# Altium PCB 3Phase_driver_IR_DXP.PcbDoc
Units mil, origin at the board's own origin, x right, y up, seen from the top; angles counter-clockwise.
Board outline 4578 x 5356 mil, 2 copper layers (Top Layer, Bottom Layer); 86 components, 55 nets, 275 pads, 76 vias.
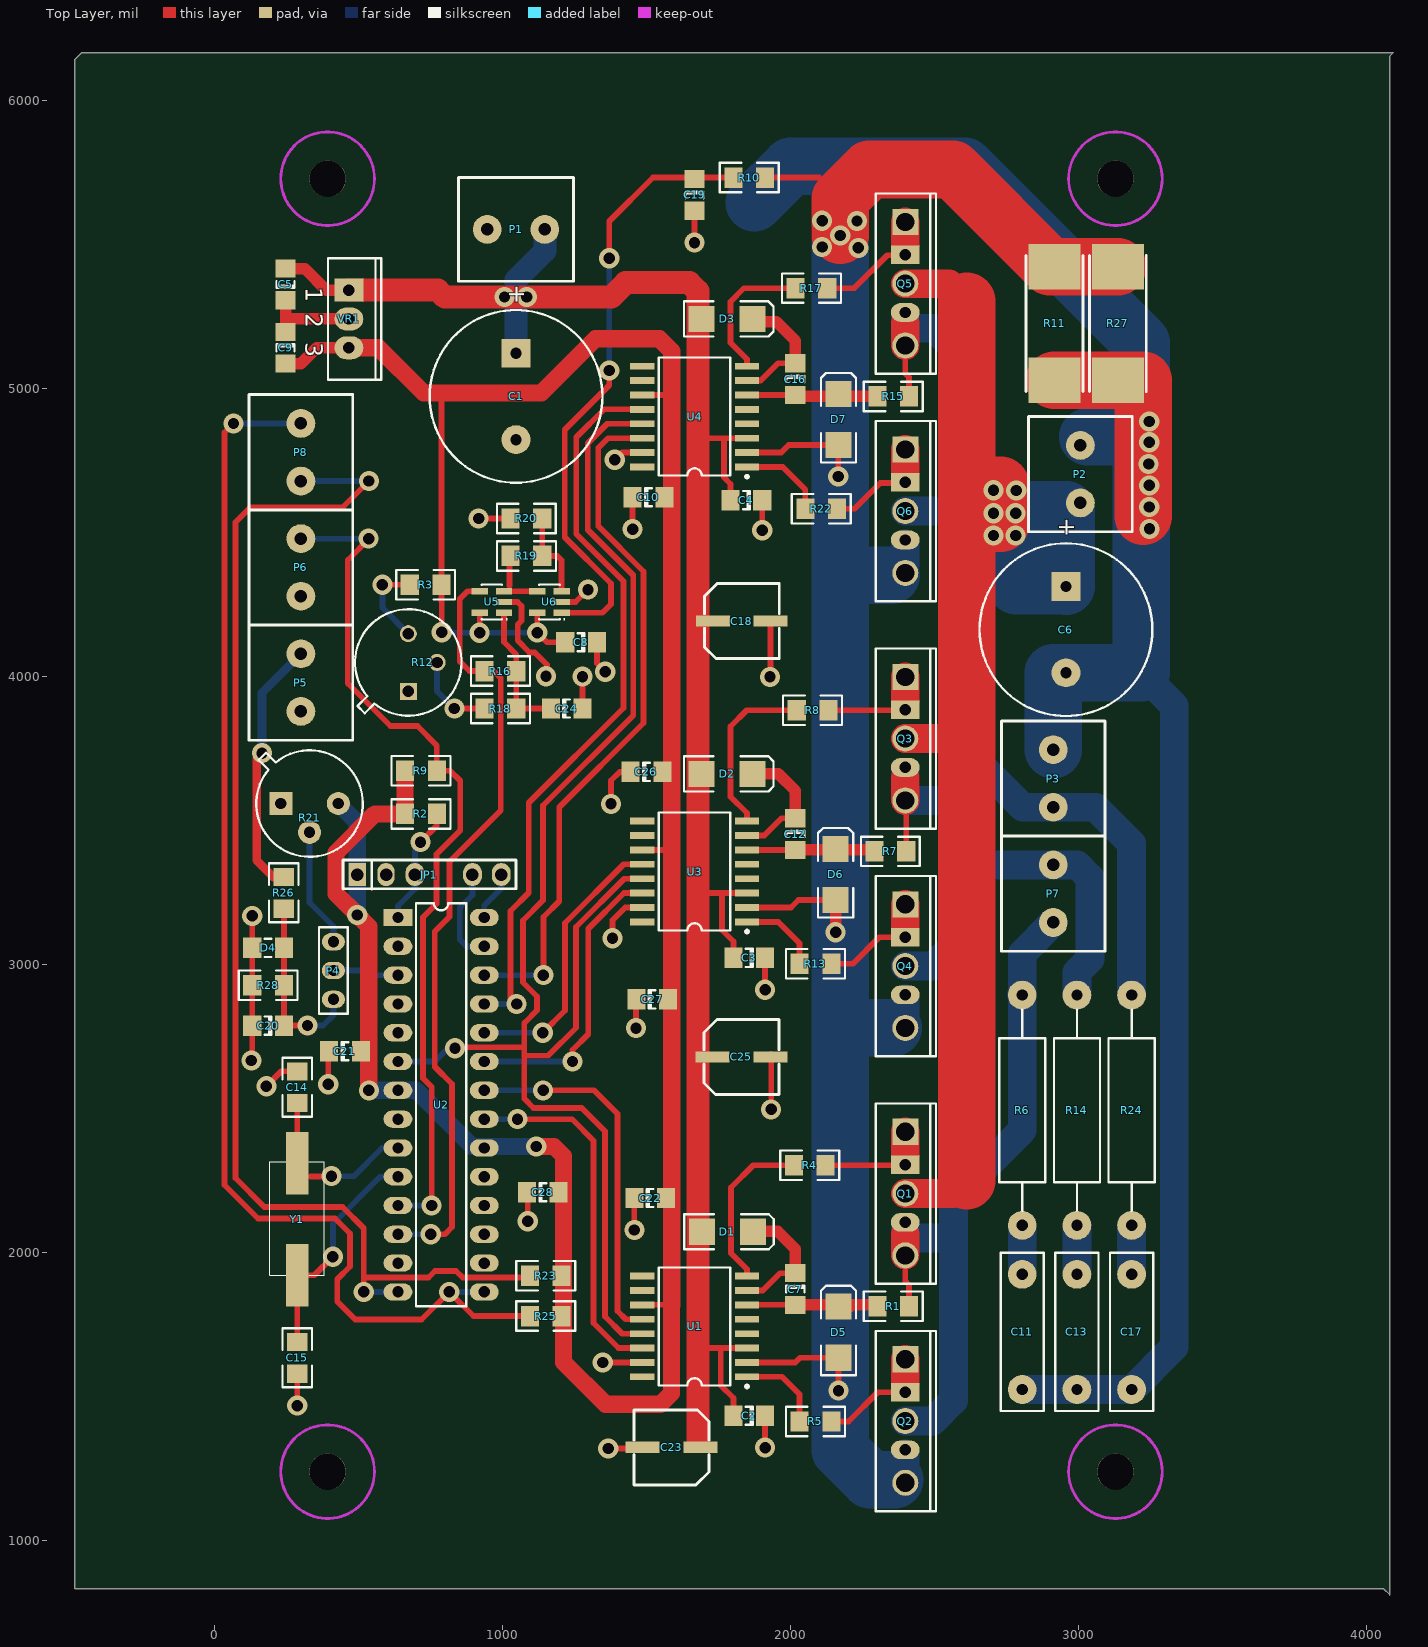
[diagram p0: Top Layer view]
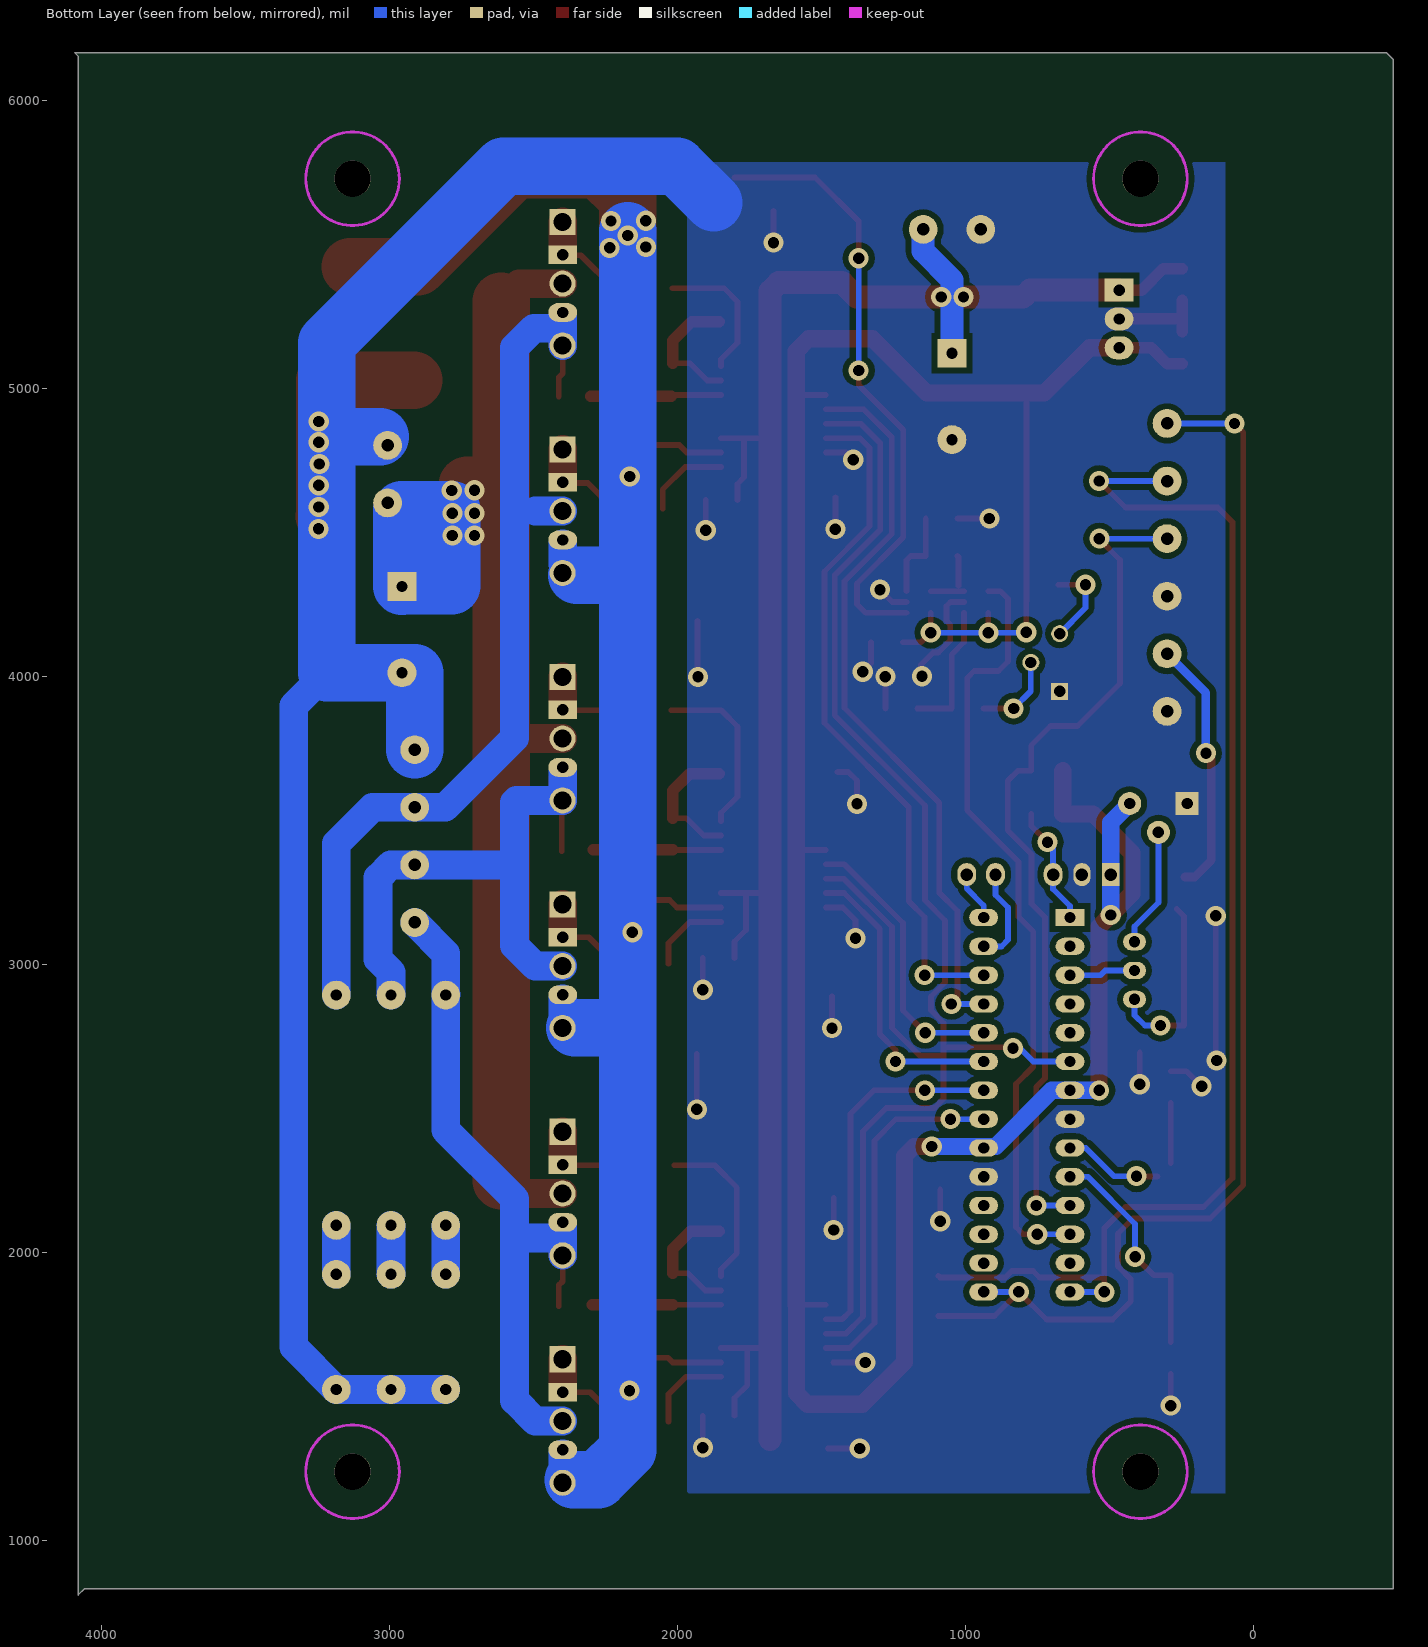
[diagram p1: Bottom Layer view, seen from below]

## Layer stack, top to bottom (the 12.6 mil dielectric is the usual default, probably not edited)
Top Layer: signal copper 1.4
Dielectric: dielectric 12.6, FR-4, Dk 4.8
Bottom Layer: signal copper 1.4

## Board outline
-484,833 4061,833 4083,811 4083,6156 4094,6167 -462,6167 -484,6145 -484,833

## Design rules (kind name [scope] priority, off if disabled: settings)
Clearance [All] p1: gap=10
PlaneConnect [All] p1: planeconnectstyle=Direct reliefexpansion=20 reliefentries=4 reliefconductorwidth=10 reliefairgap=10
PolygonConnect [All] p1: connectstyle=Direct reliefconductorwidth=10 reliefentries=4 polygonreliefangle="90 Angle"
RoutingVias [All] p1: holewidth=40 width=70 viastyle="Through Hole" minholewidth=28 minwidth=50 maxholewidth=50 maxwidth=100
SilkscreenOverComponentPads [All] p1: minsilkscreentomaskgap=10
SolderMaskExpansion [All] p1: expansion=4
TestPointUsage [All] p1: valid=0 allowmultiple=FALSE
Testpoint [All] p1: side=15 testpointundercomponent=TRUE minsize=40 maxsize=100 preferedsize=60 minholesize=0 maxholesize=40 preferedholesize=32 testpointgrid=1 style=1023 order=0123456789
Width [All] p1: maxlimit=200 minlimit=10 preferedwidth=10 toplayer_prefwidth=20 bottomlayer_prefwidth=20 minimp=50.000000 maximp=50.000000 favimp=50.000000
22 further rules are at their usual default settings.

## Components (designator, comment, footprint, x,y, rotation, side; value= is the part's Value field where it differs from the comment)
C1 "1000uF" RB7.6-15 1048,4974 r90 top
C2 "Cap Semi" C1206 1858,1434 r180 top
C3 "Cap Semi" C1206 1858,3024 r180 top
C4 "Cap Semi" C1206 1848,4614 r180 top
C5 "Cap Semi" C1206 247.57,5363 r90 top
C6 "1000uF" RB7.6-15 2958,4164 r90 top
C7 "Cap Semi" C1206 2018,1874 r270 top
C8 "Cap Semi" C1206 1274,4120 r180 top
C9 "Cap Semi" C1206 247.57,5143 r270 top
C10 "Cap Semi" C1206 1508,4624 r0 top
C11 "Cap Semi" RAD-0.4 2806,1725 r270 top
C12 "Cap Semi" C1206 2018,3454 r270 top
C13 "Cap Semi" RAD-0.4 2996,1725 r270 top
C14 "15pF" C3216-1206 288,2575 r270 top
C15 "15pF" C3216-1206 288,1635 r90 top
C16 "Cap Semi" C1206 2018,5034 r270 top
C17 "Cap Semi" RAD-0.4 3186,1725 r270 top
C18 "Cap Semi" NACZ63x8 1702,4194 r0 top
C19 "Cap Semi" C1206 1668,5674 r270 top
C20 "Cap Semi" C1206 187,2789 r180 top
C21 "Cap Semi" C1206 454,2700 r0 top
C22 "Cap Semi" C1206 1514,2190 r0 top
C23 "Cap Semi" NACZ63x8 1718,1324 r180 top
C24 "Cap Semi" C1206 1224,3890 r0 top
C25 "Cap Semi" NACZ63x8 1701,2680 r0 top
C26 "Cap Semi" C1206 1501,3670 r0 top
C27 "Cap Semi" C1206 1521,2880 r0 top
C28 "Cap Semi" C1206 1141,2210 r0 top
D1 "Diode" SMB 1782,2073 r0 top
D2 "Diode" SMB 1781,3663 r0 top
D3 "Diode" SMB 1781,5243 r0 top
D4 "D Zener" CR3216-1206 187,3059 r0 top
D5 "Diode" SMB 2168,1724 r90 top
D6 "Diode" SMB 2158,3314 r90 top
D7 "Diode" SMB 2168,4894 r90 top
JP1 "Tuskesor 6x1" SIP6P 498,3314 r0 top
P1 "Header 2" AKZ350/2-5.08 1148,5554 r180 top
P2 "Header 2" AKZ350/2-5.08 3008,4604 r90 top
P3 "Header 2" AKZ250_2 2914,3747 r270 top
P4 "Header 3" HDR1X3 414,3080 r270 top
P5 "Header 2" AKZ250_2 301,4080 r270 top
P6 "Header 2" AKZ250_2 301,4480 r270 top
P7 "Header 2" AKZ250_2 2914,3347 r270 top
P8 "Header 2" AKZ250_2 301,4680 r90 top
Q1 "MOSFET-N" TO-247_220 2400,2205.57 r270 top
Q2 "MOSFET-N" TO-247_220 2400,1415.57 r270 top
Q3 "MOSFET-N" TO-247_220 2400,3785.57 r270 top
Q4 "MOSFET-N" TO-247_220 2400,2995.57 r270 top
Q5 "MOSFET-N" TO-247_220 2400,5365.57 r270 top
Q6 "MOSFET-N" TO-247_220 2400,4575.57 r270 top
R1 "Res1" C3216-1206 2358,1814 r0 top
R2 "Res1" C3216-1206 718,3524 r180 top
R3 "Res1" C3216-1206 734,4320 r0 top
R4 "Res1" C3216-1206 2068,2304 r180 top
R5 "Res1" C3216-1206 2088,1414 r180 top
R6 "Res1" AXIAL-0.8 2806,2495 r270 top
R7 "Res1" C3216-1206 2348,3394 r0 top
R8 "Res1" C3216-1206 2078,3884 r180 top
R9 "Res1" C3216-1206 718,3674 r180 top
R10 "Res1" C3216-1206 1858,5734 r0 top
R11 "Res1" RWC5020 2918,5464 r270 top
R12 "RPot1" TO-205AF#1 674,4050 r90 top
R13 "Res1" C3216-1206 2088,3004 r180 top
R14 "Res1" AXIAL-0.8 2996,2495 r270 top
R15 "Res1" C3216-1206 2358,4974 r0 top
R16 "Res1" C3216-1206 994,4020 r180 top
R17 "Res1" C3216-1206 2074,5350 r180 top
R18 "Res1" C3216-1206 994,3890 r180 top
R19 "Res1" C3216-1206 1084,4420 r0 top
R20 "Res1" C3216-1206 1084,4550 r180 top
R21 "RPot1" TO-205AF#2 331,3560 r0 top
R22 "Res1" C3216-1206 2108,4584 r180 top
R23 "Res1" C3216-1206 1151,1920 r0 top
R24 "Res1" AXIAL-0.8 3186,2495 r270 top
R25 "Res1" C3216-1206 1151,1780 r0 top
R26 "Res1" C3216-1206 241,3250 r270 top
R27 "Res1" RWC5020 3138,5464 r270 top
R28 "Res1" C3216-1206 187,2929 r0 top
U1 "IR2112" SO-G16/D10.4 1668,1744 r90 top
U2 "PIC18F2431-I/SP" PDIP300-28 788,2514 r270 top
U3 "IR2112" SO-G16/D10.4 1668,3324 r90 top
U4 "IR2112" SO-G16/D10.4 1668,4904 r90 top
U5 "LMV321M5" MA05B 964,4260 r90 top
U6 "LMV321M5" MA05B 1164,4260 r90 top
VR1 "Volt Reg" SFM-T3/A4.7V 467.57,5243 r270 top
Y1 "10MHz" Q36M 288,2205 r270 top

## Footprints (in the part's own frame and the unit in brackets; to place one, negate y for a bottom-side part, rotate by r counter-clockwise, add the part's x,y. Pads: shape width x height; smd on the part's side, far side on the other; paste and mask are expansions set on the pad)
AKZ250_2 [mm]
  round 2.54 hole 1.1: 1(0,0) 2(5.08,0)
  silkscreen extent -2.54,-4.57 7.62,4.57
AKZ350/2-5.08 [mm]
  round 2.54 hole 1.1: 1(0,0) 2(5.08,0)
  silkscreen extent -2.54,-4.57 7.62,4.57
AXIAL-0.8 [mm] "Adjustable Inductor; 2 Leads"
  round 2.54 hole 1: 1(-10.16,0) 2(10.16,0)
  silkscreen extent -8.89,-2.03 8.89,2.03
C1206 [mm] "Chip Capacitor; Body 3.2 x 1.6 mm (LxW typ)"
  rect 1.6x1.8 smd: 1(-1.4,0) 2(1.4,0)
  silkscreen extent -0.3,-0.8 0.3,0.8
C3216-1206 [mm]
  rect 1.6x1.8 smd: 1(-1.398,0) 2(1.402,0)
  silkscreen extent -2.6,-1.3 2.6,1.3
CR3216-1206 [mm] "Chip Resistor; Body 3.2 x 1.6 mm (LxW typ)"
  rect 1.6x1.8 smd: 1(-1.4,0) 2(1.4,0)
  silkscreen extent -0.3,-0.8 0.3,0.8
HDR1X3 [mil] "Connector; Header; 3 Position"
  oval 60x80 hole 39.37: 1(0,0) 2(100,0) 3(200,0)
  silkscreen extent -50,-50 250,50
MA05B [mm] "SOT-23/SC-74A; 5 Leads; Body 3 x 3 mm, inc. leads (LxW max)"
  rect 0.55x1.45 smd: 1(-0.95,-1.075) 2(0,-1.075) 3(0.95,-1.075) 4(0.95,1.075) 5(-0.95,1.075)
  silkscreen extent -1.57,-1.35 1.55,0.9
NACZ63x8 [mm]
  rect 3x1 smd: 1(0.762,0) 2(5.842,0)
  silkscreen extent 0,-3.3 6.6,3.3
PDIP300-28 [mil] "DIP, Plastic, Skinny; 28 Leads; Row Spacing 7.62 mm; Pitch 2.54 mm"
  rect 60x100 hole 39.37: 1(-650,-150)
  oval 60x100 hole 39.37: 2(-550,-150) 3(-450,-150) 4(-350,-150) 5(-250,-150) 6(-150,-150) 7(-50,-150) 8(50,-150) 9(150,-150) 10(250,-150) 11(350,-150) 12(450,-150) 13(550,-150) 14(650,-150) 15(650,150) 16(550,150) 17(450,150) 18(350,150) 19(250,150) 20(150,150) 21(50,150) 22(-50,150) 23(-150,150) 24(-250,150) 25(-350,150) 26(-450,150) 27(-550,150) 28(-650,150)
  silkscreen extent -700,-88 700,88
Q36M [mm]
  rect 5.5x2 smd: 1(-2.7,0) 2(7.2,0)
  silkscreen extent -2.8,-2.4 7.2,2.4
RAD-0.4 [mm] "Servo Motor; 2 Leads"
  round 2.54 hole 1: 1(-5.08,0) 2(5.08,0)
  silkscreen extent -6.98,-1.91 6.98,1.91
RB7.6-15 [mm] "Polarized Capacitor (Radial); 2 Leads"
  rect 2.54x2.54 hole 1: 1(3.81,0)
  round 2.54 hole 1: 2(-3.81,0)
  silkscreen extent -7.62,-7.62 7.62,7.62
RWC5020 [mm]
  rect 4x4.6 smd: 1(1.006,0.003) 2(11.006,0.003)
  silkscreen extent 0.01,-2.5 12.01,2.5
SFM-T3/A4.7V [mil]
  rect 80x100 hole 39.37: 1(-99.91,0)
  oval 80x100 hole 39.37: 2(0.09,0) 3(100.09,0)
  silkscreen extent -211,-73 211,112
SIP6P [mil]
  rect 60x80 hole 43.31 mask+4: 1(-1.22,-0.5)
  oval 60x80 hole 43.31 mask+4: 2(98.78,-0.5)
  oval 65x80 hole 43.31 mask+4: 3(198.78,-0.5) 5(398.78,-0.5) 6(498.78,-0.5)
  silkscreen extent -51,-50 550,50
SMB [mm] "DO-214-AA/SMB; 2 C-Bend Leads; Body 5.3 x 3.6 mm, inc. leads (LxW)"
  rect 2.3x2.3 smd: 1(-2.25,0) 2(2.25,0)
  silkscreen extent -3.8,-1.55 4.1,1.55
SO-G16/D10.4 [mm] "Small Outline, Plastic; 16 Leads; Body Width 7.5 mm"
  rect 0.6x2.15 smd: 1(-4.445,-4.625) 2(-3.175,-4.625) 3(-1.905,-4.625) 4(-0.635,-4.625) 5(0.635,-4.625) 6(1.905,-4.625) 7(3.175,-4.625) 8(4.445,-4.625) 9(4.445,4.625) 10(3.175,4.625) 11(1.905,4.625) 12(0.635,4.625) 13(-0.635,4.625) 14(-1.905,4.625) 15(-3.175,4.625) 16(-4.445,4.625)
  silkscreen extent -5.42,-4.75 5.2,3.15
TO-205AF#1 [mm] "Can; 3 Leads; Pin Circle Dia. 5.08 mm; Lead Dia. 0.53 mm (max)"
  rect 1.5x1.5 hole 1: 1(-2.54,0)
  round 1.5 hole 1: 2(0,-2.54) 3(2.54,0)
  silkscreen extent -4.7,-4.7 4.7,4.7
TO-205AF#2 [mm] "Can; 3 Leads; Pin Circle Dia. 5.08 mm; Lead Dia. 0.53 mm (max)"
  rect 2.032x2.032 hole 1: 1(-2.54,0)
  round 2.032 hole 1: 2(0,-2.54) 3(2.54,0)
  silkscreen extent -4.7,-4.7 4.7,4.7
TO-247_220 [mm] "SIP with Mounting Hole; 3 Leads; Body 20 x 15.6 x 5 mm (typ); Pitch 5.45 mm"
  rect 2.3x2.3 hole 1.6: 1(-5.45,0)
  rect 1.651x2.54 hole 1: 1(-2.54,0)
  round 2.3 hole 1.6: 2(0,0) 3(5.45,0)
  oval 1.651x2.54 hole 1: 3(2.54,0)
  silkscreen extent -7.95,-2.6 7.95,2.7

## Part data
C1 C6: library part "Cap Pol1", "Polarized Capacitor (Radial)"
C2 C3 C4 C5 C7 C8 C9 C10 C11 C12 C13 C16 C17 C18 C19 C20 C21 C22 C23 C24 C25 C26 C27 C28: "Capacitor (Semiconductor SIM Model)"
C14 C15: library part Cap, "Capacitor"
D1 D2 D3 D5 D6 D7: "Default Diode"
D4: library part Diode, "Default Diode"
JP1: library part "Header 6", "Header, 6-Pin"
P1 P2 P3 P5 P6 P7 P8: "Header, 2-Pin"
P4: "Header, 3-Pin"
Q1 Q2 Q3 Q4 Q5 Q6: "N-Channel MOSFET"
R1 R2 R3 R4 R5 R6 R7 R8 R9 R10 R11 R13 R14 R15 R16 R17 R18 R19 R20 R22 R23 R24 R25 R26 R27 R28: "Resistor"
R12 R21: "Potentiometer"
U1 U3 U4: library part FAN7384
U2: "Enhanced FLASH Microcontroller with nanoWatt Technology, High Performance PWM and A/D, 16K FLASH, 28-Pin Skinny PDIP, Standard Volt Range, Industrial Temperature"
U5 U6: "Single General-Purpose, Low-Voltage Rail-to-Rail Output Operational Amplifier"
VR1: "Voltage Regulator"
Y1: library part XTAL, "Crystal Oscillator"

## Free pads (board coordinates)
  round 125.98 hole 125.98: 0(393.54,1239.84) 1(3129.76,1239.84) 2(3129.76,5730.04) 3(393.54,5730.04)

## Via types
v1: diameter 70, hole 39.37, Top Layer to Bottom Layer, 76 vias

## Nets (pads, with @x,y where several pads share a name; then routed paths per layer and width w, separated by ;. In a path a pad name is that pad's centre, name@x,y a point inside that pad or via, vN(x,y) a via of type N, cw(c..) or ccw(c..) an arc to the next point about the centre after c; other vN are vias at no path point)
+5: C8.2 C9.2 C10.2 C21.2 C22.2 C26.2 C27.2 C28.2 JP1.1 R2.2 R3.2 R9.2 R21.3 R23.2 R25.2 U1.11 U2.7 U2.20 U3.11 U4.11 U5.5 U6.5 VR1.3 | length 10526.2
  Top Layer w20: 789.2,4984.71 R3.2 789.2,4261.8 790,4261 v1(790,4155) ; v1(921.68,4153.32) U5.5 ; U6.5 v1(1121.68,4153.68) 1155.35,4120 C8.2 ; U1.11 1587.89,1819 ; U3.11 1581,3399 ; U4.11 1589,4979
  Top Layer w40: C9.2 300.88,5087.88 355.91,5142.91 VR1.3
  Top Layer w60: VR1.3 570.09,5142.91 727.09,4985.91 1135.91,4985.91 1324,5174 1546,5174 1589,5131 1589,4979 1589,4624 1589,2997 1588.94,2996.94 1588.94,1817.94 ; v1(537,2564) 537,3133 v1(496.78,3173.22) 423,3247 423,3389 558,3524 R2.2 R9.2 ; v1(1118,2369.12) 1179.88,2369.12 1213,2336 1213,1620 1359,1474 1550,1474 1587.89,1511.89 1587.89,1819
  Bottom Layer w20: v1(790,4155) 791.68,4153.32 v1(921.68,4153.32) v1@1121.32,4153.32
  Bottom Layer w60: R21.3 496.78,3494.22 JP1.1 v1(496.78,3173.22) ; v1(537,2564) U2.7 701,2564 895.88,2369.12 v1(1118,2369.12)
+12: C1.1 C2.2 C3.2 C4.2 C5.2 C18.1 C23.1 C25.1 D1.1 D2.1 D3.1 P1.1 U1.3 U3.3 U4.3 VR1.1 | length 7169.8
  Top Layer w20: 1683.42,3249 1763,3249 ; 1686.42,4829 1770,4829 ; 1695,1669 1759,1669 ; C4.2 1792.88,4670.12 1770,4693 1770,4829 ; C2.2 1802.88,1495.12 1759,1539 1759,1669 ; C3.2 1802.88,3081.12 1763,3121 1763,3249 ; U1.3 1759,1669 ; U3.3 1763,3249 ; U4.3 1770,4829
  Top Layer w40: C5.2 313.88,5418.12 389.09,5342.91 VR1.1
  Top Layer w80: VR1.1 777.09,5342.91 801,5319 v1(1008,5319) v1(1085,5319) 1379,5319 1429,5369 1650,5369 1679.42,5339.58 1679.42,5234 1679.42,3664 1679.42,2894 1679.42,2074 1679.42,1351.58
  Bottom Layer w80: C1.1 1048,5379 1148,5479 P1.1
GND: C1.2 C2.1 C3.1 C4.1 C5.1 C6.2 C8.1 C9.1 C10.1 C11.2 C13.2 C14.1 C15.1 C17.2 C18.2 C19.2 C20.2 C21.1 C22.1 C23.2 C24.2 C25.2 C26.1 C27.1 C28.1 D4.1 JP1.2 P1.2 P2.2 P3.1 P5.2 P6.2 R11.2 R12.1 R20.2 R21.1 R27.2 R28.1 U1.15 U2.8 U2.19 U3.15 U4.15 U5.2 U6.2 VR1.2 | length 11234.5
  Top Layer w20: v1@131.88,2675.88 C20.2 v1(131.88,3169.8) ; v1(181,2578) 233.03,2630.03 C14.1 ; v1(288,1469.17) C15.1 ; v1@396,2590.8 C21.1@396,2695.8 ; v1(918,4550) R20.2 ; U5.2 1053,4260 1067,4246 1067,4195 1054,4182 1054,4126 1095,4085 1113,4085 1156,4042 1156,4006 v1(1152,4002) ; v1(1088.88,2109.2) C28.1@1088.88,2220 ; U6.2 1255,4260 v1(1298,4303) ; C24.2 v1(1279.12,4000.8) ; C8.1 1329.12,4046.88 v1(1358,4018) ; v1(1349.2,1619) U1.15@1460,1619 ; v1(1368.2,1320) C23.2@1479,1320 ; v1(1378,3559) 1378,3640 1408,3670 C26.1 ; v1(1383,3092) 1383,3155 1427,3199 U3.15 ; v1(1391,4754) 1416,4779 U4.15 ; v1(1452.88,4513.2) C10.1 ; v1(1458.88,2079.2) C22.1 ; v1(1464.76,2780.2) C27.1@1464.76,2891 ; v1(1668,5508.09) C19.2 ; v1(1903.12,4509.12) C4.1 ; v1(1913.12,1323.2) C2.1 ; v1(1913.12,2913.2) C3.1 ; v1@1932,4002 C18.2 ; v1(1934,2498) C25.2@1934,2690
  Top Layer w40: C9.1 C5.1 ; 247.65,5242.91 VR1.2
  Top Layer w200: R11.2 R27.2 3225.71,5030.71 3225.71,4559.29 3227,4558
  Bottom Layer w100: C11.2 C13.2 C17.2 3334,1673 3334,3900 3220,4014
  Bottom Layer w200: 1876,5647 2002,5773 2607,5773 3220,5160 v1@3220,4834 ; P3.1 2914,4014 3220,4014 v1@3220,4834 ; P2.2@3033,4834 v1@3220,4834
  other v1: 396,2585 128.88,2667.88 1930,4000 3248,4514 3247,4590 3247,4665 3245,4739 3247,4815 3247,4887
NetC7_1: C7.1 D1.2 U1.7 | length 463.4
  Top Layer w20: U1.7 1905,1869 1965.12,1929.12 C7.1
  Top Layer w40: D1.2@1856.58,2074 1957,2074 2018,2013 C7.1
NetC7_2: C7.2 D5.2 R1.1 U1.6 | length 490.5
  Top Layer w20: U1.6 C7.2@2017.88,1819
  Top Layer w40: C7.2 2201.7,1818.88 D5.2@2208,1812.58 ; D5.2@2167.88,1819 R1.1@2298,1819
NetC11_1: C11.1 R6.2 | length 170
  Bottom Layer w100: C11.1 R6.2
NetC12_1: C12.1 D2.2 U3.7 | length 474.6
  Top Layer w20: U3.7 1910,3449 1970.12,3509.12 C12.1
  Top Layer w40: D2.2@1856.58,3664 1959,3664 2018,3605 C12.1
NetC12_2: C12.2 D6.2 R7.1 U3.6 | length 442.8
  Top Layer w20: U3.6 C12.2@2017.88,3399
  Top Layer w40: C12.2 R7.1@2292.97,3398.88
NetC13_1: C13.1 R14.2 | length 170
  Bottom Layer w100: C13.1 R14.2
NetC14_2: C14.2 U2.9 Y1.1 | length 550.8
  Top Layer w20: Y1.1 C14.2 ; 334.3,2265 v1@405,2265
  Bottom Layer w20: v1(407,2266) 485,2266 583,2364 U2.9
NetC15_2: C15.2 U2.10 Y1.2 | length 790
  Top Layer w20: C15.2 Y1.2 347.54,1921.54 v1(412,1986)
  Bottom Layer w20: v1(412,1986) 412,2100 576,2264 U2.10
NetC16_1: C16.1 D3.2 U4.7 | length 460.5
  Top Layer w20: U4.7 1898,5029 1958.12,5089.12 C16.1
  Top Layer w40: D3.2@1856.58,5234 1952,5234 2018,5168 C16.1
NetC16_2: C16.2 D7.2 R15.1 U4.6 | length 447.9
  Top Layer w20: U4.6 C16.2@2017.88,4979
  Top Layer w40: C16.2@2022.88,4974 R15.1
NetC17_1: C17.1 R24.2 | length 170
  Bottom Layer w100: C17.1 R24.2
NetC19_1: C19.1 R10.1 U6.1 | length 2138.7
  Top Layer w20: U6.1 1348.6,4222.6 1378,4252 1378,4324 1217,4485 1217,4858 1372,5013 v1(1372,5064) ; v1(1372,5454) 1372,5582 1524,5734 R10.1
  Bottom Layer w20: v1(1372,5064) v1(1372,5454)
NetC20_1: C20.1 D4.2 P4.3 R26.2 R28.2 | length 656.9
  Top Layer w20: R26.2@267,3193.8 242.12,3168.91 D4.2 C20.1 v1(324,2789)
  Bottom Layer w20: v1(324,2789) 378,2789 414,2825 P4.3
NetC24_1: C24.1 R16.1 R18.1 U5.1 | length 470.1
  Top Layer w20: U5.1 1006.32,4183.68 1006.32,4120.71 1049.03,4078 R16.1 R18.1 C24.1
NetD5_1: D5.1 D6.1 D7.1 Q2.3 Q4.3 Q6.3 R10.2 R11.1 R27.1 U1.2 U3.2 U4.2 | length 7778.3
  Top Layer w20: U1.2 2018,1619 2034.42,1635.42 D5.1 v1(2168,1521) ; U3.2 2003,3199 2029.42,3225.42 D6.1 ; U4.2 1969,4779 1995.42,4805.42 D7.1 2167,4804.42 v1(2167,4696) ; R10.2 2101,5734
  Top Layer w40: v1(2158,3113) D6.1
  Top Layer w200: v1(2174,5533) 2174,5661 2275,5762 2565,5762 2902.59,5424.41 R11.1 R27.1
  Bottom Layer w100: 2400,1249 Q2.3@2400,1301 ; Q4.3@2400,2823 Q4.3@2400,2881 ; Q6.3@2400,4391 Q6.3@2400,4461
  Bottom Layer w200: v1@2174,5550 v1(2174,5533) 2174,4353 ; 2351,4353 2174,4353 ; Q4.3@2358,2781 2174,2781 ; Q2.3@2363,1212 2277,1212 2174,1315 2174,2781 ; 2174,2781 2174,4353
  other v1: 2237,5490 2111,5493 2232,5583 2111,5584
NetJP1_3: JP1.3 R2.1 U2.1 | length 415.9
  Top Layer w20: v1(716,3426) 773.03,3483.03 R2.1
  Bottom Layer w20: U2.1 638,3204 696.78,3262.78 JP1.3 696.78,3406.78 v1(716,3426)
NetJP1_5: JP1.5 U2.27 | length 339.2
  Bottom Layer w20: JP1.5 896.78,3242.78 853,3199 853,3087 876,3064 U2.27
NetJP1_6: JP1.6 U2.28 | length 173.8
  Bottom Layer w20: U2.28 938,3206 996.78,3264.78 JP1.6
NetP3_2: P3.2 Q5.3 Q6.2 R15.2 R24.1 | length 3300.8
  Top Layer w20: Q5.3@2400,5151 2400,5054 2413.2,5040.8 R15.2
  Top Layer w100: Q5.3@2400,5151 2400,5229
  Bottom Layer w100: Q6.2 2495.57,4575.57 ; Q5.3@2400,5151 2400,5211 ; Q5.3@2400,5248 2400,5211 ; R24.1 3186,3421 3060,3547 P3.2 2808,3547 2567,3788 2567,5144 2500,5211 2400,5211
NetP4_1: P4.1 R21.2 | length 414.4
  Bottom Layer w20: R21.2 331,3216 414,3133 P4.1
NetP4_2: P4.2 U2.3 | length 230.6
  Bottom Layer w20: P4.2 516,2980 532,2964 565,2964 U2.3
NetP5_1: P5.1 R26.1 | length 896.8
  Top Layer w30: v1(166,3735) 147.03,3716.03 147.03,3362.97 204.97,3305.03 R26.1@239,3305.03
  Bottom Layer w30: v1(166,3735) 166,3945 P5.1
NetP6_1: P6.1 R9.1 U2.11 | length 3007.2
  Top Layer w20: v1(536,4480) 536,4478 464,4406 464,3977 612,3829 706,3829 773.03,3761.97 R9.1 819,3674 854,3639 854,3466 772,3384 772,3212 725,3165 725,2606 755,2576 v1(755,2164)
  Bottom Layer w20: P6.1 v1(536,4480) ; U2.11 v1(755,2164)
NetP7_1: P7.1 Q3.3 Q4.2 R7.2 R14.1 | length 2130.1
  Top Layer w20: R7.2 Q3.3@2403.2,3567.8
  Top Layer w100: Q3.3@2400,3571 2400,3649
  Bottom Layer w100: Q4.2 2495.57,2995.57 2567,3067 2567,3564 2560,3571 2400,3571 Q3.3@2400,3668 ; 2568,3347 P7.1 2997,3347 3041,3303 3041,3019 2996,2974 R14.1
NetP7_2: P7.2 Q1.3 Q2.2 R1.2 R6.1 | length 2513.6
  Top Layer w20: Q1.3@2400,1991 2400,1901 2413.2,1887.8 R1.2
  Top Layer w100: Q1.3@2400,1991 2400,2065
  Bottom Layer w100: Q2.2 2495.57,1415.57 2567,1487 2567,2187 2806,2426 R6.1 ; Q1.3@2400,1991 2400,2051 ; Q1.3@2400,2088 2400,2051 ; 2557,2051 2400,2051 ; R6.1@2804,2897 R6.1 ; P7.2 2806,3039 R6.1
NetP8_1: P8.1 R23.1 U2.14 | length 4493.2
  Top Layer w20: v1(519,1864) 519,1917 ; v1(537,4680) 445,4588 125,4588 73.88,4536.88 73.88,2259.12 174,2159 445,2159 519,2085 519,1917 ; R23.1 1089.97,1914 863,1914 840,1937 767,1937 744,1914 522,1914 519,1917
  Bottom Layer w20: P8.1 v1(537,4680) ; v1(519,1864) U2.14
NetP8_2: P8.2 R25.1 U2.15 | length 4542.3
  Top Layer w20: v1(67,4880) 36,4849 36,2235 152,2119 419,2119 471,2067 471,1952 427,1908 427,1831 490,1768 720,1768 v1(816,1864) 900,1780 R25.1
  Bottom Layer w20: v1(67,4880) P8.2 ; v1(816,1864) U2.15
NetQ1_1: Q1.1 R4.1 | length 317.1
  Top Layer w20: R4.1 Q1.1@2362,2304
  Top Layer w100: 2400,2342 Q1.1@2400,2420.13
NetQ2_1: Q2.1 R5.1 | length 394.2
  Top Layer w20: R5.1 2203,1414 2304.57,1515.57 Q2.1@2400,1515.57 ; 2384,1551 2400,1551
  Top Layer w100: 2400,1551 Q2.1@2400,1630.13
NetQ3_1: Q3.1 R8.1 | length 311.1
  Top Layer w20: R8.1 Q3.1@2364,3884
  Top Layer w100: 2400,3920 Q3.1@2400,4000.13
NetQ4_1: Q4.1 R13.1 | length 402.6
  Top Layer w20: R13.1 2218,3004 2309.57,3095.57 Q4.1@2400,3095.57 ; Q4.1@2370.28,3125.28 2382,3137 2400,3137
  Top Layer w100: 2400,3137 Q4.1@2400,3210.13
NetQ5_1: Q5.1 R17.1 | length 356.3
  Top Layer w20: R17.1 2223,5350 2337,5464 Q5.1@2361,5464
  Top Layer w100: 2400,5503 Q5.1@2400,5580.13
NetQ6_1: Q6.1 R22.1 | length 368.7
  Top Layer w20: R22.1 2224,4584 2313,4673 2362,4673 2400,4711
  Top Layer w100: 2400,4711 Q6.1@2400,4790.13
NetR3_1: R3.1 R12.3 | length 302.2
  Top Layer w20: v1(584,4320) R3.1
  Bottom Layer w20: v1(584,4320) 584,4240 R12.3
NetR4_2: R4.2 U1.8 | length 580.5
  Top Layer w20: U1.8 1850.09,1942.91 1795,1998 1795,2227 1872,2304 1929,2304 R4.2
NetR5_2: R5.2 U1.1 | length 302.1
  Top Layer w20: U1.1 1972,1569 2032.8,1508.2 R5.2
NetR8_2: R8.2 U3.8 | length 605.6
  Top Layer w20: U3.8 1850.09,3526.91 1793,3584 1793,3828 1849,3884 1910,3884 R8.2
NetR12_2: R12.2 R18.2 | length 289.6
  Top Layer w20: v1(834,3890) R18.2
  Bottom Layer w20: R12.2 774,3950 v1(834,3890)
NetR13_2: R13.2 U3.1 | length 284.5
  Top Layer w20: U3.1 1959,3149 2032.8,3075.2 R13.2
NetR16_2: R16.2 U2.12 U5.4 | length 2688.3
  Top Layer w20: v1(752,2064) 801,2064 826,2089 826,2586 766,2646 766,3116 817,3167 817,3358 995,3536 995,3996 971,4020 R16.2 886,4020 853,4053 853,4271 879.4,4297.4 U5.4
  Bottom Layer w20: U2.12 v1(752,2064)
NetR17_2: R17.2 U4.8 | length 492.9
  Top Layer w20: U4.8 1850.09,5102.91 1793,5160 1793,5303 1840,5350 R17.2
NetR19_1: R19.1 U5.3 U6.4 | length 220.9
  Top Layer w20: U5.3 U6.4 ; 1025,4316.08 1025,4416.03 R19.1
NetR19_2: R19.2 R20.1 U6.3 | length 310.6
  Top Layer w20: R19.2@1139.03,4420.17 R20.1 ; R19.2 1191,4420 1206.32,4404.68 U6.3
NetR22_2: R22.2 U4.1 | length 301.6
  Top Layer w20: U4.1 1974,4729 2052.8,4650.2 R22.2
NetU1_12: U1.12 U2.22 | length 1278.5
  Top Layer w20: v1(1142,2564) 1319,2564 1400,2483 1400,1798 1429,1769 U1.12
  Bottom Layer w20: U2.22 v1(1142,2564)
NetU1_13: U1.13 U2.6 U3.13 U4.13 | length 5212
  Top Layer w20: v1(836,2710) 836,2708 839,2705 848,2705 857,2714 1076,2714 ; U1.13 1417,1719 1357,1779 1357,2422 1276,2503 1109,2503 1077,2535 1077,2684 ; U3.13 1424,3299 1256,3131 1256,2781 1159,2684 1077,2684 ; U4.13 1365,4879 1297,4811 1297,4511 1455,4353 1455,3866 1142,3553 1142,3224 1072,3154 1072,2939 1121,2890 1121,2842 1077,2798 1077,2684
  Bottom Layer w20: U2.6 766,2664 812,2710 v1(836,2710)
NetU1_14: U1.14 U2.21 | length 1248
  Top Layer w20: v1(1053,2464) 1242,2464 1317,2389 1317,1756 1404,1669 U1.14
  Bottom Layer w20: U2.21 v1(1053,2464)
NetU2_23: U2.23 U3.14 | length 1028.1
  Top Layer w20: v1(1244,2664) 1244,2704 1299,2759 1299,3125 1423,3249 U3.14
  Bottom Layer w20: U2.23 v1(1244,2664)
NetU2_24: U2.24 U3.12 | length 968.3
  Top Layer w20: v1(1141,2764) 1218,2841 1218,3145 1422,3349 U3.12
  Bottom Layer w20: U2.24 v1(1141,2764)
NetU2_25: U2.25 U4.12 | length 2588.1
  Top Layer w20: v1(1050,2864) 1029,2885 1029,3187 1092,3250 1092,3563 1421,3892 1421,4332 1257,4496 1257,4832 1354,4929 U4.12
  Bottom Layer w20: U2.25 v1(1050,2864)
NetU2_26: U2.26 U4.14 | length 2411.8
  Top Layer w20: v1(1143,2964) 1143,3166 1198,3221 1198,3547 1491,3840 1491,4366 1334,4523 1334,4796 1367,4829 U4.14
  Bottom Layer w20: U2.26 v1(1143,2964)
VB: C6.1 P2.1 Q1.2 Q3.2 Q5.2 | length 4984
  Top Layer w100: Q1.2 2567.57,2205.57 ; Q3.2 2610.43,3785.57 ; Q5.2 2551.43,5365.57 2613,5304
  Top Layer w200: 2613,2251 2613,4534 2613,4751 ; 2613,5304 2613,4751 ; 2622,4534 2732,4534 2732,4666 2629,4666 2613,4682 2613,4751
  Bottom Layer w200: C6.1@2957,4314 2955,4316 2785,4316 2785,4581 2958,4581 C6.1
  other v1: 2706,4491 2783,4491 2706,4568 2783,4568 2785,4647 2706,4648
pads on no net: U1.4 U1.5 U1.9 U1.10 U1.16 U2.2 U2.4 U2.5 U2.13 U2.16 U2.17 U2.18 U3.4 U3.5 U3.9 U3.10 U3.16 U4.4 U4.5 U4.9 U4.10 U4.16

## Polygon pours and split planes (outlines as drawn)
GND on Bottom Layer "Bottom Layer-No Net" (solid, remove dead copper, pour order 1000): 99,1165 1962,1165 1967,1170 1967,5788 103,5788 99,5792 99,1165

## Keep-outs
Keep-Out Layer:
  circle w10: c3129.76,1239.84 r162.59
  circle w10: c393.54,1239.84 r162.59
  circle w10: c3129.76,5730.04 r162.59
  circle w10: c393.54,5730.04 r162.59

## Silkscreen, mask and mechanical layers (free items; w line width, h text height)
Mechanical 1:
  circle w10: c393.54,5730.04 r62.99
  lines w20: -0.17,5883 -0.17,1062.99 3425.03,1062.99 3425.03,5883 7,5883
